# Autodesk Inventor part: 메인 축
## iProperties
Company: 한국ATC센터
Created: 2014-10
Part Number: 메인 축
Document SubType Name: Modeling
Designer: KYOUNG IL JANG
Density: 1 g/cm^3
Mass: 29.2926 g
Surface Area: 74.3518 cm^2
Volume: 29.2926 cm^3
Author: KYOUNG IL JANG
Revision Number: 1
